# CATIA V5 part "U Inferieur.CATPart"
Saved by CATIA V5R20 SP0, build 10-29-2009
Part number: U Inferieur
Bounding box of the stored display mesh (mm): x -31.5 to -16.5, y 28.5 to 32.5, z -19.5 to -2.5
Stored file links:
  E:\Boulot\SeaTech\2eme ANNEE\FabricationAdditive\TP_MOSM_CREM\Projet Sauterelle de serrage\CAO Assemblage Sauterelle\U Inferieur.CATPart
  E:\Boulot\SeaTech\2eme ANNEE\FabricationAdditive\TP_MOSM_CREM\Projet Sauterelle de serrage\CAO Assemblage Sauterelle\Sauterelle_horizontale_05120-06.CATPart
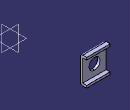
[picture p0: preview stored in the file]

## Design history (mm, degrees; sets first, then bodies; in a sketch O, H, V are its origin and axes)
Body1 (main body)
  Solid1 "05120-06_9": solid without history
